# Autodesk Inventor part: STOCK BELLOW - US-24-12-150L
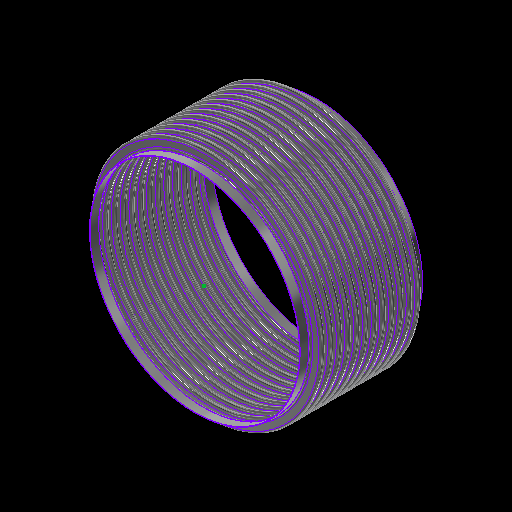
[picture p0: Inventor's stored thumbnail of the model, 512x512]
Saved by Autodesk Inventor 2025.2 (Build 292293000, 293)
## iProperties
Category: 16 GA (0.060 THICK)
RuleStatus: InUse
Created: 2024-01
Part Number: STOCK BELLOW - US-24-12-150L
Project: =STOCK BELLOWS: <Stock Number><SFILL>
Material: ASTM A240-304
Description: =STOCK BELLOWS: <Stock Number>, <SID_> I.D., <SOD_> O.D., <SPLY_> PLY, <Category>, <SNET_CONS> CONS.<PITCH_><STANGENT_> TANGENT<SFILL>
Document SubType Name: Sheet Metal
Designer: GS
Stock Number: U.S-24-12-150L
Surface Area: 38369.6 cm^2
Volume: 2910.39 cm^3
Sheet Metal Rule: Default
Appearance: STAINLESS STEEL
Mass: 23449.8 g
Density: 8.05729 g/cm^3
THK: 0.036
ID: 3.500
OD: 4.250
CONS_: 2
PITCH: 0.500
TANGENT: 0.500
BELLOWS_UPSET: 0.000
d79: 1.000
d82: 1.000
d83: 26.000
d84: 24.000
d174: 8
d214: 8
STHK_: 0.060
SID_: 24.000
SOD_: 26.500
SPITCH_: 1.000
STANGENT__: 1.000
SBELLOWS_UPSET_: 0.000
SDIFF_TAN: 1.000
d252: 2
d275: 2
d287: 0.050
d289: 0.500
d290: 0.000
SOD_NECK: 24 1/8
PLY: 1
PSET: 4.178
PBAR: 1.035
COUNTER: 1.500
NET_TUBE: 3.071
CONS: 2
S_CONS: 0
NET_CONS: 2
ID_M: 88.90 mm
OD_M: 107.95 mm
THK_M: 0.91 mm
ID_U: 3.500 in
OD_U: 4.250 in
THK_U: 0.036 in
TANGENT2: 0.500
TAN_TO_TAN: 1.000 in
d80: 2.571
d81: 10
SID: 2.375
SCONS_: 12
SPITCH: 0.250
STANGENT_: 1.000
SBELLOWS_UPSET: 0.000
SNET_CONS: 12
SS_CONS: 0
SCONS: 8
d190: 8
d191: 1
d192: 1
d193: 8
d194: 0
SIZE: 24.00
PRESSURE: 150
d230: 8
STANGENT: 4.000
SPLY_: 1
d233: 8
d234: 0
d263: 2
d265: 1
d268: 2
d269: 0
d286: 2
d288: 1
d291: 2
d292: 0
SREROLL: 0.750
BLETP: 1.000 ul
PRES_Copy: 85
MATTABLE: 20 GA (0.036 THICK)
PART_NUMBER: U.S-24-12-150L
PITCH_: =, <SPITCH_> PITCH,
CFILL: .
SFILL: .
MESH: ,
COMP: 2.21
EXT: 1.11
LAT: 0.26
ANG: 458
ASR: 4528
LSR: 27063
ANSR: 5668
PRES: 150
COMPM: 22.1
EXTM: 11.05
LATM: 2.60
ASRM: 792.989
PRESM: 10.342
LSRM: 4739.543
ANSRM: 992.637
TEMPMIN: 20
TEMPMAX: 800
TEMPMINM: -7
TEMPMAXM: 427
WEIGHTM: 23.450
WEIGHT: 51.698
Author: GS
Keywords: 20 GA (0.036 THICK)
Comments: =STOCK BELLOW - <STOCK NUMBER>
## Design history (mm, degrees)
sketch "Sketch2"
  geometry: L1 (0, -177.245)-(0, 562.856) reference; L2 (45.364, 0)-(44.45, 0); L3 (48.082, -2.718)-(50.343, -2.718); L4 (48.082, -3.632)-(50.343, -3.632); L5 (50.343, -9.982)-(48.082, -9.982); L6 (50.343, -9.068)-(48.082, -9.068); L7 (45.364, -12.7)-(44.45, -12.7); L8 (48.082, 0)-(48.082, -12.7); L9 (50.343, -6.35)-(53.975, -6.35); L10 (44.45, 0)-(44.45, -12.7); L11 (20.376, 102.841)-(20.376, 101.926); L12 (58.262, 457.127)-(58.262, 349.177); L13 (58.262, 444.427)-(58.262, 336.477); L14 (93.133, -58.817)-(93.133, -71.517); L15 (118.746, -66.401)-(118.746, -66.401); L16 (50.343, -9.068)-(50.343, -9.982); L17 (48.082, -9.068)-(48.082, -9.982); L18 (48.082, -9.525)-(50.343, -9.525); L19 (53.975, 0)-(53.975, -12.7); L20 (-50.343, -9.068)-(-50.343, -9.982); L21 (-50.343, -2.718)-(-48.082, -2.718); L22 (-50.343, -3.632)-(-48.082, -3.632); L23 (-48.082, -9.068)-(-50.343, -9.068); L24 (-50.343, -9.525)-(-48.082, -9.525); L25 (-48.082, -9.982)-(-50.343, -9.982); L26 (-48.082, -9.068)-(-48.082, -9.982); L27 (-44.45, 0.653)-(-44.45, -12.047); L28 (-48.082, -6.35)-(-44.45, -6.35); L29 (-50.343, 0.653)-(-50.343, -12.7); L30 (-53.061, 0)-(-53.975, 0); L31 (-53.975, 0)-(-53.975, -12.7); L32 (-53.061, -12.7)-(-53.975, -12.7); A1 r 2.718 centre (48.082, 0) between (45.364, 0) and (48.082, -2.718); A2 r 3.632 centre (48.082, 0) between (44.45, 0) and (48.082, -3.632); A3 r 3.632 centre (50.343, -6.35) between (50.343, -9.982) and (50.343, -2.718); A4 r 2.718 centre (50.343, -6.35) between (50.343, -9.068) and (50.343, -3.632); A5 r 2.718 centre (48.082, -12.7) between (48.082, -9.982) and (45.364, -12.7); A6 r 3.632 centre (48.082, -12.7) between (48.082, -9.068) and (44.45, -12.7); A7 r 3.175 centre (50.343, -6.35) between (50.343, -9.525) and (53.518, -6.35); A8 r 3.175 centre (48.082, -12.7) between (48.082, -9.525) and (44.907, -12.7); A9 r 2.718 centre (-50.343, -12.7) between (-50.343, -9.982) and (-53.061, -12.7); A10 r 2.718 centre (-48.082, -6.35) between (-48.082, -9.068) and (-48.082, -3.632); A11 r 3.175 centre (-48.082, -6.35) between (-48.082, -9.525) and (-44.907, -6.35); A12 r 3.632 centre (-48.082, -6.35) between (-48.082, -9.982) and (-48.082, -2.718); A13 r 3.175 centre (-50.343, -12.7) between (-50.343, -9.525) and (-53.518, -12.7); A14 r 3.632 centre (-50.343, -12.7) between (-50.343, -9.068) and (-53.975, -12.7); A15 r 2.718 centre (-50.343, 0) between (-53.061, 0) and (-50.343, -2.718); A16 r 3.632 centre (-50.343, 0) between (-53.975, 0) and (-50.343, -3.632); 10 further points
  constraints: 62 end point, 38 point on circle, 20 tangent, 16 centre point, 12 parallel, 9 midpoint, 7 vertical, 6 coincident, 6 concentric, 6 point on line, 4 equal radius, 4 perpendicular, 3 horizontal, 1 collinear, 1 horizontal alignment, 10 other
  dimensions: "THK" = 0.9144 distance of L11.start L11.end; "ID" = 88.9 distance of L11.end point (20.376, 13.026); "OD" = 107.95 distance of L12.start L12.end; "PITCH" = 12.7 distance of L12.start L13.start; "TANGENT" = 12.7 distance of L14.start L14.end; "BELLOWS_UPSET" = 0 distance of L15.start L15.end; "d43" = 88.9 diameter of L10 L1 (= ID); "d44" = 107.95 diameter of L9.end L1 (= OD); "d45" = 0.9144 distance between parallel lines of L5 L6 (computed from THK, PLY); "d46" = 3.6322 radius of A3 (computed from PITCH, THK, PLY); "UPSET_PITCH" = 12.7 distance of L2.end L7.end (derived); "SIDEWALL_ANGLE" = 360 deg dimension on L3 L9 (derived); "CON_GAP" = 5.4356 distance of point (48.082, -9.068) point (48.082, -3.632) (derived); "TAN1" = 4.98728 dimension on A8 (derived); "TAN2" = 4.98728 dimension on A7 (derived); "LEG1" = 2.2606 distance of L18.start L18.end (derived); "d278" = 0.9144 distance between parallel lines of L25 L23 (derived); "d279" = 3.6322 radius of A12 (derived); "d280" = 12.7 distance of L30.end L31.end (derived); "d281" = 360 deg dimension on L21 L28 (derived); "d282" = 5.4356 distance of point (-50.343, -9.068) point (-50.343, -3.632) (derived); "d283" = 4.98728 dimension on A13 (derived); "d284" = 4.98728 dimension on A11 (derived); "d285" = 2.2606 distance of L24.start L24.end (derived); "d293" = 88.9 diameter of L27 L1 (derived); "d294" = 107.95 diameter of L31 L1 (derived)
  node "Sketch Rectangular Pattern1" dims "d31" = 25.4, "ID" = 88.9
  node "Sketch Rectangular Pattern2" dims "d39" = 25.4, "PITCH" = 12.7
revolve "CONS" stored, may be unused: angle "d48" = 90 deg
node "BELLOW MIDPLANE"
pattern_linear "Rectangular Pattern2" dims "d52" = 12.7 (= UPSET_PITCH)
sketch "Sketch5"
  geometry: C1 r 45.364 at (0, 0) reference; C2 r 44.45 at (0, 0) reference
extrude "TANGENT" new body sketch "Sketch5" distance "d53" = 12.7 (= TANGENT); taper "d54" = 0 deg
revolve "SAMETAN" stored, may be unused: angle "d65" = 90 deg
revolve "DIFFTAN" stored, may be unused: angle "d70" = 90 deg
sketch "Sketch9"
  geometry: L1 (53.319, 0)-(-53.319, 0) reference; L2 (0, -17.78)-(0, 17.78) reference; L3 (38.085, 0)-(-38.085, 0); L4 (38.085, -11.906)-(38.085, 11.906); L5 (25.385, -11.906)-(25.385, 11.906); L6 (13.15, 11.906)-(13.15, -11.906); L7 (-25.385, -11.906)-(-25.385, 11.906); L8 (-38.085, -11.906)-(-38.085, 11.906); L9 (37.291, -11.906)-(37.291, 11.906); L10 (38.085, -11.906)-(37.291, -11.906); L11 (38.085, 11.906)-(37.291, 11.906); L12 (13.546, 11.906)-(12.753, 11.906); L13 (12.753, 11.906)-(12.753, -11.906); L14 (12.753, -11.906)-(13.546, -11.906); L15 (13.546, -11.906)-(13.546, 11.906); L16 (-13.546, 11.906)-(-13.546, -11.906); L17 (-13.15, 11.906)-(-13.15, -11.906); L18 (-13.546, -11.906)-(-12.753, -11.906); L19 (-12.753, -11.906)-(-12.753, 11.906); L20 (-12.753, 11.906)-(-13.546, 11.906); L21 (-38.085, -11.906)-(-37.291, -11.906); L22 (-37.291, -11.906)-(-37.291, 11.906); L23 (-37.291, 11.906)-(-38.085, 11.906); L24 (-38.085, 11.906)-(-38.085, -11.906); L25 (38.085, -0.397)-(-38.085, -0.397); L26 (-38.085, -0.397)-(-38.085, 0.397); L27 (-38.085, 0.397)-(38.085, 0.397); L28 (38.085, 0.397)-(38.085, -0.397); L29 (-38.085, 11.906)-(38.085, 11.906); L30 (38.085, 11.906)-(38.085, 12.7); L31 (38.085, 12.7)-(-38.085, 12.7); L32 (-38.085, 12.7)-(-38.085, 11.906); L33 (38.085, -11.906)-(-38.085, -11.906); L34 (-38.085, -11.906)-(-38.085, -12.7); L35 (-38.085, -12.7)-(38.085, -12.7); L36 (38.085, -12.7)-(38.085, -11.906); 30 further points
  constraints: 68 end point, 13 midpoint, 13 parallel, 8 horizontal, 7 perpendicular, 6 equal length, 3 point on line, 2 vertical, 14 other
  dimensions: "d115" = 23.8125 distance of L4.start L4.end (derived); "d116" = 12.7 distance between parallel lines of L4 L5 (derived); "d117" = 12.23516 distance between parallel lines of L5 L6 (derived); "d125" = 38.53427 distance between parallel lines of L7 L6 (derived); "d127" = 12.7 distance between parallel lines of L8 L7 (derived); "d128" = 24.93516 distance between parallel lines of L6 L4 (derived); "d130" = 76.16943 distance between parallel lines of L8 L4 (derived); "RULER_THK" = 0.79375 distance between parallel lines of L4 L9; "d135" = 0.79375 distance of L13.end L14.end (derived); "d138" = 26.29911 distance of L13.end L16.end (derived); "d143" = 0.79375 distance of L22.end L8.end (derived); "d144" = 0.79375 distance between parallel lines of L27 L25 (derived)
extrude "RULER" join sketch "Sketch9" distance "d149" = 0.79375 (derived); taper "d150" = 0 deg
extrude "BARS" join sketch "Sketch9" distance "d151" = 0.79375 (derived); taper "d152" = 0 deg
pattern_linear "Rectangular Pattern4" dims "d155" = 26.29911 (derived)
sketch "Sketch13"
  geometry: L1 (93.149, -52.467)-(93.149, -77.867); L2 (306.324, 0)-(304.8, 0); L3 (306.324, -25.4)-(304.8, -25.4); L4 (329.438, -19.812)-(311.912, -19.812); L5 (329.438, -18.288)-(311.912, -18.288); L6 (329.438, -12.7)-(336.55, -12.7); L7 (311.912, -5.588)-(329.438, -5.588); L8 (311.912, 0)-(311.912, -25.4); L9 (304.8, 0)-(304.8, -25.4); L10 (58.254, 176.669)-(58.254, -496.431); L11 (58.254, 151.269)-(58.254, -521.831); L12 (58.254, 100.469)-(58.254, -572.631); L13 (58.254, 75.069)-(58.254, -598.031); L14 (58.254, 49.669)-(58.254, -623.431); L15 (58.254, 24.269)-(58.254, -648.831); L16 (58.254, -1.131)-(58.254, -674.231); L17 (58.254, 125.869)-(58.254, -547.231); L18 (20.376, 103.45)-(20.376, 101.926); L19 (311.912, -7.112)-(329.438, -7.112); L20 (0, -844.411)-(0, 346.849) reference; L21 (-67.31, 0)-(403.86, 0) reference; A1 r 5.588 centre (311.912, 0) between (306.324, 0) and (311.912, -5.588); A2 r 5.588 centre (311.912, -25.4) between (311.912, -19.812) and (306.324, -25.4); A3 r 7.112 centre (311.912, -25.4) between (311.912, -18.288) and (304.8, -25.4); A4 r 5.588 centre (329.438, -12.7) between (329.438, -18.288) and (329.438, -7.112); A5 r 7.112 centre (329.438, -12.7) between (329.438, -19.812) and (329.438, -5.588); A6 r 7.112 centre (311.912, 0) between (304.8, 0) and (311.912, -7.112); 6 further points; 1 other entity
  constraints: 38 end point, 15 point on circle, 9 tangent, 6 centre point, 6 parallel, 5 vertical alignment, 4 point on line, 4 vertical, 3 coincident, 3 concentric, 2 collinear, 2 equal radius, 1 horizontal, 1 perpendicular, 23 other
  dimensions: "SBELLOWS_UPSET_" = 0 distance of point (118.762, -66.401) point (118.762, -66.401); "STOTAL_THK_BELLOW__" = 1.524 distance between parallel lines of L4 L5 (derived); "d224" = 7.112 radius of A5 (derived); "d225" = 25.4 distance of L2.end L3.end (derived); "SSIDEWALL_ANGLE_" = 360 deg dimension on L7 L6 (derived); "SSCON_GAP_" = 11.176 distance of point (311.912, -18.288) point (311.912, -7.112) (derived); "d235" = 609.6 diameter of L9 L20 (derived); "d236" = 673.1 diameter of L6.end L20 (derived)
  node "Sketch Rectangular Pattern4" dims "d228" = 25.4
  node "Sketch Rectangular Pattern5" dims "d229" = 25.4
revolve "SBELLOW" stored, may be unused: angle "d197" = 90 deg
pattern_linear "Rectangular Pattern5" dims "d204" = 25.4 (derived)
revolve "STANGENT" stored, may be unused: angle "d240" = 90 deg
revolve "SSAMETAN" stored, may be unused: angle "d241" = 90 deg
revolve "SDIFFTAN" stored, may be unused: angle "d246" = 90 deg
revolve "INVCON" stored, may be unused: angle "d295" = 90 deg
pattern_linear "Rectangular Pattern6" dims "d298" = 12.7 (derived)
revolve "INVTANGENT" stored, may be unused: angle "d302" = 90 deg
revolve "INVSAMETAN" stored, may be unused: angle "d307" = 90 deg
revolve "INVDIFFTAN" stored, may be unused: angle "d312" = 90 deg
sketch "ID BELLOW MOUNT CALC"
  geometry: L1 (44.45, 0)-(38.1, 0); L2 (38.1, 0)-(38.1, 12.7); L3 (38.1, 12.7)-(44.45, 12.7); L4 (44.45, 12.7)-(44.45, 0); L5 (36.513, 12.7)-(35.598, 12.7); L6 (35.598, 12.7)-(35.598, 0); L7 (35.598, 0)-(36.513, 0); L8 (36.513, 0)-(36.513, 12.7); L9 (0, -2.54)-(0, 15.24) reference; L10 (-8.89, 0)-(53.34, 0) reference; 1 further point
  constraints: 16 end point, 5 parallel, 2 collinear, 2 horizontal, 2 perpendicular
  dimensions: "d314" = 12.7 distance of L5.end L6.end (derived); "d315" = 0.9144 distance of L5.start L5.end (derived); "IG" = 1.5875 distance between parallel lines of L2 L8; "PIPE_OD" = 88.9 diameter of L4 L9; "PIPE_WALL" = 6.35 distance of L2.end L3.end; "ID_MT_BELLOW" = 71.1962 diameter of L6 L9 (derived)
revolve "CFILL" stored, may be unused: angle "d320" = 90 deg
pattern_linear "Rectangular Pattern7" dims "d323" = 12.7 (derived)
revolve "SFILL" stored, may be unused: angle "d324" = 90 deg
pattern_linear "Rectangular Pattern8" dims "d327" = 25.4 (derived)
node "STOCK BELLOW MIDPLANE"
node "BELLOW"
sketch "Sketch6"
  geometry: L1 (-12.7, 45.364)-(0, 45.364); L2 (0, 45.364)-(0, 44.45); L3 (0, 44.45)-(-12.7, 44.45); L4 (-12.7, 44.45)-(-12.7, 45.364); L5 (10.16, 0)-(-60.96, 0) reference; L6 (-38.1, -89.422)-(-38.1, 153.44) reference; 1 further point
  constraints: 8 end point, 2 parallel, 1 horizontal, 1 perpendicular
  dimensions: "d61" = 12.7 distance of L2.end L3.end (derived); "d62" = 0.9144 distance of L1.end L2.end (derived); "d63" = 88.9 diameter of L3 L5 (derived); "d64" = 25.4 distance between parallel lines of L4 L6 (derived)
sketch "Sketch12"
  geometry: 1 further point
sketch "Sketch14"
  geometry: L1 (-25.4, 306.324)-(0, 306.324); L2 (0, 306.324)-(0, 304.8); L3 (0, 304.8)-(-25.4, 304.8); L4 (-25.4, 304.8)-(-25.4, 306.324); L5 (5.08, 0)-(-30.48, 0) reference; L6 (0, -61.265)-(0, 367.589) reference; 1 further point
  constraints: 8 end point, 2 parallel, 1 collinear, 1 horizontal, 1 perpendicular
  dimensions: "d237" = 1.524 distance of L3.end L1.start (derived); "d238" = 609.6 diameter of L3 L5 (derived); "d239" = 25.4 distance of L1.start L1.end (derived); "SOD_NECK" = 612.648 diameter of L1 L5 (derived)
sketch "Sketch15"
  geometry: L1 (-61.265, 0)-(367.589, 0) reference; L2 (304.8, -304.8)-(306.324, -304.8); L3 (306.324, -304.8)-(306.324, -330.2); L4 (306.324, -330.2)-(304.8, -330.2); L5 (304.8, -330.2)-(304.8, -304.8); L6 (0, -398.78)-(0, 81.28) reference; 1 further point
  constraints: 8 end point, 2 parallel, 1 horizontal, 1 perpendicular
  dimensions: "d205" = 25.4 distance of L4.end L2.start (derived); "d206" = 1.524 distance of L3.end L4.end (derived); "d207" = 609.6 diameter of L5 L6 (derived); "d208" = 304.8 distance between parallel lines of L1 L2 (derived)
node "TANGENT_"
node "SAME_TAN"
sketch "Sketch8"
  geometry: L1 (45.364, -25.4)-(44.45, -25.4); L2 (44.45, -25.4)-(44.45, -38.1); L3 (44.45, -38.1)-(45.364, -38.1); L4 (45.364, -38.1)-(45.364, -25.4); L5 (0, -48.26)-(0, 22.86) reference; L6 (-89.422, 0)-(153.44, 0) reference; 1 further point
  constraints: 8 end point, 2 parallel, 1 horizontal, 1 perpendicular
  dimensions: "d66" = 88.9 diameter of L2 L5 (derived); "TOTAL_THK_BELLOW" = 0.9144 distance of L2.end L3.end (derived); "d68" = 25.4 distance between parallel lines of L1 L6 (derived); "d69" = 12.7 distance of L1.end L2.end (derived)
node "DIFF_TAN"
node "Sketch Rectangular Pattern3" dims "d138" = 26.29911 (derived), "d141" = 25.4
node "SBELLOW_"
node "STANGENT_"
node "SSAME_TAN"
sketch "Sketch16"
  geometry: L1 (306.324, -304.8)-(304.8, -304.8); L2 (304.8, -304.8)-(304.8, -330.2); L3 (304.8, -330.2)-(306.324, -330.2); L4 (306.324, -330.2)-(306.324, -304.8); L5 (0, -398.78)-(0, 81.28) reference; L6 (-61.265, 0)-(367.589, 0) reference; 1 further point
  constraints: 8 end point, 2 parallel, 1 horizontal, 1 perpendicular
  dimensions: "SDIFF_TAN" = 25.4 distance of L3.end L1.start; "d243" = 1.524 distance of L2.end L3.end (derived); "d244" = 304.8 distance between parallel lines of L1 L6 (derived); "d245" = 609.6 diameter of L2 L5 (derived)
node "SDIFF_TAN"
body "Solid15"
sketch "Sketch17"
  geometry: L1 (53.975, 12.7)-(53.061, 12.7); L2 (53.061, 12.7)-(53.061, 0); L3 (53.061, 0)-(53.975, 0); L4 (53.975, 0)-(53.975, 12.7); L5 (0, -2.54)-(0, 15.24) reference; L6 (-10.795, 0)-(64.77, 0) reference; 2 further points
  constraints: 8 end point, 2 parallel, 1 horizontal, 1 midpoint, 1 perpendicular, 1 point on line
  dimensions: "INVTANGENT" = 12.7 distance of L3.end L1.start (derived); "d300" = 0.9144 distance of L1.start L1.end (derived); "d301" = 107.95 diameter of L4 L5 (derived)
body "Solid16"
sketch "Sketch18"
  geometry: L1 (53.975, -25.4)-(53.061, -25.4); L2 (53.061, -25.4)-(53.061, -38.1); L3 (53.061, -38.1)-(53.975, -38.1); L4 (53.975, -38.1)-(53.975, -25.4); L5 (-10.795, 0)-(64.77, 0) reference; L6 (0, -48.26)-(0, 22.86) reference; 1 further point
  constraints: 8 end point, 2 parallel, 1 horizontal, 1 perpendicular
  dimensions: "d303" = 25.4 distance between parallel lines of L1 L5 (derived); "d304" = 12.7 distance of L3.end L1.start (derived); "d305" = 0.9144 distance of L2.end L3.end (derived); "d306" = 107.95 diameter of L4 L6 (derived)
body "Solid17"
sketch "Sketch19"
  geometry: L1 (53.975, -25.4)-(53.061, -25.4); L2 (53.061, -25.4)-(53.061, -38.1); L3 (53.061, -38.1)-(53.975, -38.1); L4 (53.975, -38.1)-(53.975, -25.4); L5 (0, -48.26)-(0, 22.86) reference; L6 (-10.795, 0)-(64.77, 0) reference; 1 further point
  constraints: 8 end point, 2 parallel, 1 horizontal, 1 perpendicular
  dimensions: "d308" = 12.7 distance of L1.end L2.end (derived); "d309" = 107.95 diameter of L4 L5 (derived); "d310" = 0.9144 distance of L2.end L3.end (derived); "d311" = 25.4 distance between parallel lines of L1 L6 (derived)
body "Solid18"
body "Solid19"
body "Solid20"
other parameters: "BMPL" = -152.4, "PSET" = 106.1212 (computed from OD, THK, PLY) [user parameter], "PBAR" = 26.29911 (= 0.570796 x PITCH + OD - ID) [user parameter; used in 1 equation term], "COUNTER" = 15 [user parameter], "NET_TUBE" = 77.99823 (computed from CONS_, PBAR, TANGENT) [user parameter], "S_CONS" = 0 [user parameter; used in 1 equation term], "ID_M" = 88.9 (= ID) [user parameter], "OD_M" = 107.95 (= OD) [user parameter], "THK_M" = 0.9144 (= THK) [user parameter], "ID_U" = 88.9 (= ID) [user parameter], "OD_U" = 107.95 (= OD) [user parameter], "THK_U" = 0.9144 (= THK) [user parameter], "D_UNITS" = 0 [user parameter], "TANGENT2" = 12.7 [user parameter], "TAN_TO_TAN" = 25.4 [user parameter], "OD_NECK" = 90.7288 [user parameter], "d79" = 25.4, "d80" = 65.29823 [user parameter], "d82" = 25.4, "d83" = 660.4, "d84" = 609.6, "sa_0" = 4, "FRAME_THK" = 0.79375 [user parameter], "CON_FLAT" = 12.23516 [user parameter], "SID" = 60.325 [user parameter], "SPITCH" = 6.35 [user parameter], "STANGENT_" = 25.4 [user parameter], "SBELLOWS_UPSET" = 0 [user parameter], "SS_CONS" = 0 [user parameter], "STAN_TO_TAN_" = 304.8 [user parameter], "d100" = 1.524 [user parameter], "d191" = 25.4 [user parameter], "d194" = 0 [user parameter], "STANGENT" = 101.6 [user parameter], "d234" = 0 [user parameter], "SUPSET_PITCH_" = 25.4 [user parameter], "d269" = 0 [user parameter], "d287" = 1.27, "d289" = 12.7, "d290" = 0, "d292" = 0 [user parameter], "Thickness" = 3.048 (derived), "KFactor" = 4.4, "BendRadius" = 3.048 (derived), "BendReliefWidth" = 3.048 (derived), "BendReliefDepth" = 1.524 (derived), "CornerReliefSize" = 12.192 (derived), "SeamGap" = 0.00508, "MinimumRemnant" = 6.096 (derived), "TransitionRadius" = 3.048 (derived), "JacobiRadiusSize" = 3.048 (derived), "GapSize" = 3.048 (derived), "SREROLL" = 19.05 [user parameter], "CUR_STK_PITCH" = 25.4 [user parameter], "d328" = -152.4 (derived), "ASR" = 45280 [user parameter], "LSR" = 270630 [user parameter], "ANSR" = 56680 [user parameter], "BLETP" = 1 [user parameter], "ASRM" = 7929.8864 [user parameter], "PRESM" = 103.41975 [user parameter], "LSRM" = 47395.4319 [user parameter], "ANSRM" = 9926.3684 [user parameter], "TEMPMIN" = 2664.83333 [user parameter], "TEMPMAX" = 6998.16667 [user parameter], "TEMPMINM" = 2664.83333 [user parameter], "TEMPMAXM" = 6998.16667 [user parameter], "WEIGHT" = 234.49814 [user parameter], "WEIGHTM" = 0.2345 [user parameter]
